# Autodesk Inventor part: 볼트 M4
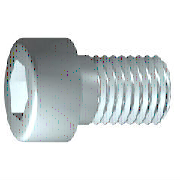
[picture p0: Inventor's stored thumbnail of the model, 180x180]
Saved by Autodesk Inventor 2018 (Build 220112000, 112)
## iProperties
IsCustomPart: 0
Created: 2009-02
Part Number: 볼트 M4
Material: 강철, 연강
Description: 6각머리 태핑 나사
Document SubType Name: Modeling
Standard: KS B 1003
Standards Organization: KS
Language: ko-KR
Size Designation: M 4 x 12
Categories: <MemberInstance><Categories><Category DisplayName="조임쇠" InternalName="e4da775c-781d-43d5-af7c-5136215cf5a6" Mnemonic="FSTN"><Category DisplayName="볼트" InternalN
Density: 1 g/cm^3
Appearance: 차가운 흰색
Author: pww
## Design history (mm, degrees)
sketch "스케치1"
  geometry: L1 (-1, 0)-(12, 0); L2 (12, 0)-(12, 2); L3 (12, 2)-(1.75, 2); L4 (1.75, 2)-(1.32, 2); L5 (1.32, 2)-(0, 2); L6 (0, 2)-(0, 3.5); L7 (0, 3.5)-(-4, 3.5); L8 (-4, 3.5)-(-4, 1.732); L9 (-4, 1.732)-(-2, 1.732); L10 (-2, 1.732)-(-1, 0); L11 (-7.2, 0)-(15.2, 0) reference; L12 (0, -0.7)-(0, 4.2) reference; L13 (1.75, 2)-(0, 2)
  constraints: 22 end point, 6 parallel, 2 collinear, 2 perpendicular, 1 horizontal, 1 point on line
  dimensions: "d1" = 10.25 distance from line of L3.end L2 (= GEL); "d2" = 0.42952 distance of L4.end L3.end (computed from GAL); "d3" = 4 distance between parallel lines of L8 L6 (= KOH); "d4" = 2 distance of L8.end L9.end (= INTI); "d5" = 60 deg angle of L10 L1; "d6" = 4 diameter of L3 L1 (= GD); "d7" = 4 diameter of L5 L1 (= BDM); "d8" = 3.4641 diameter of L9 L1 (= 1.1547 x SW); "d9" = 7 diameter of L7 L1 (= KOD); "d26" = 12 distance between parallel lines of L12 L2 (= NLG)
revolve "본체" sketch "스케치1" stored, may be unused: angle "d10" = 90 deg
sketch "스케치2"
  geometry: L1 (0, -4.9)-(0, 4.9) reference; L2 (-4.9, 0)-(4.9, 0) reference; L3 (1.732, 0)-(0.866, -1.5); L4 (0.866, -1.5)-(-0.866, -1.5); L5 (-0.866, -1.5)-(-1.732, 0); L6 (-1.732, 0)-(-0.866, 1.5); L7 (-0.866, 1.5)-(0.866, 1.5); L8 (0.866, 1.5)-(1.732, 0); 2 further points
  constraints: 12 end point, 1 coincident, 1 horizontal alignment, 1 point on line, 12 other
extrude "슬롯" join sketch "스케치2" stored distance "d11" = 10; taper "d12" = 0 deg
workplane "Work Plane1"
fillet "Fillet2" dims "d30" = 0.1 (= R)
body "Solid1"
fillet "모깎기1" dims "d17" = 0.4 (= RR)
feature "스레드" dims "d13" = 10.25 (= GEL), "d14" = 0
chamfer "모따기1" distance "d15" = 0.42941 (= -0.5 x SPD + 0.5 x GD); stored, may be unused: second distance "d16" = 0.42941 (= GUL), angle "d27" = 45 deg
other parameters: "GD" = 4 (= NND) [user parameter; used in 2 equation terms], "NLG" = 12 [user parameter; used in 1 equation term], "GEL" = 10.25 [user parameter; used in 2 equation terms], "KOD" = 7 [user parameter; used in 1 equation term], "KOH" = 4 [user parameter; used in 1 equation term], "INTI" = 2 [user parameter; used in 1 equation term], "GAL" = 0.42941 (= 0.61345 x PTC) [user parameter; used in 1 equation term], "GUL" = 0.42941 (= 0.61345 x PTC) [user parameter; used in 1 equation term], "BDM" = 4 (= NND) [user parameter; used in 1 equation term], "SW" = 3 [user parameter; used in 2 equation terms], "RR" = 0.4 [user parameter; used in 1 equation term], "SPD" = 3.14117 (= NND - 1.2269 x PTC) [user parameter; used in 1 equation term], "d19" = 0, "d28" = 0, "d29" = 0, "R" = 0.1 [user parameter; used in 1 equation term], "PHH" = 0.2 [user parameter], "GD1" = 3.14117 (= THREADDIA - 1.2269 x PTC) [user parameter], "THREADDIA" = 4 [user parameter; used in 1 equation term], "FAWI" = 45 deg [user parameter], "TPU" = 14.28571 (computed from PTC) [user parameter], "PTC" = 0.7 [user parameter; used in 5 equation terms], "NND" = 4 [user parameter; used in 3 equation terms], "TOA" = 30 deg [user parameter], "E0" = 3.465 (= 1.155 x SW) [user parameter]
